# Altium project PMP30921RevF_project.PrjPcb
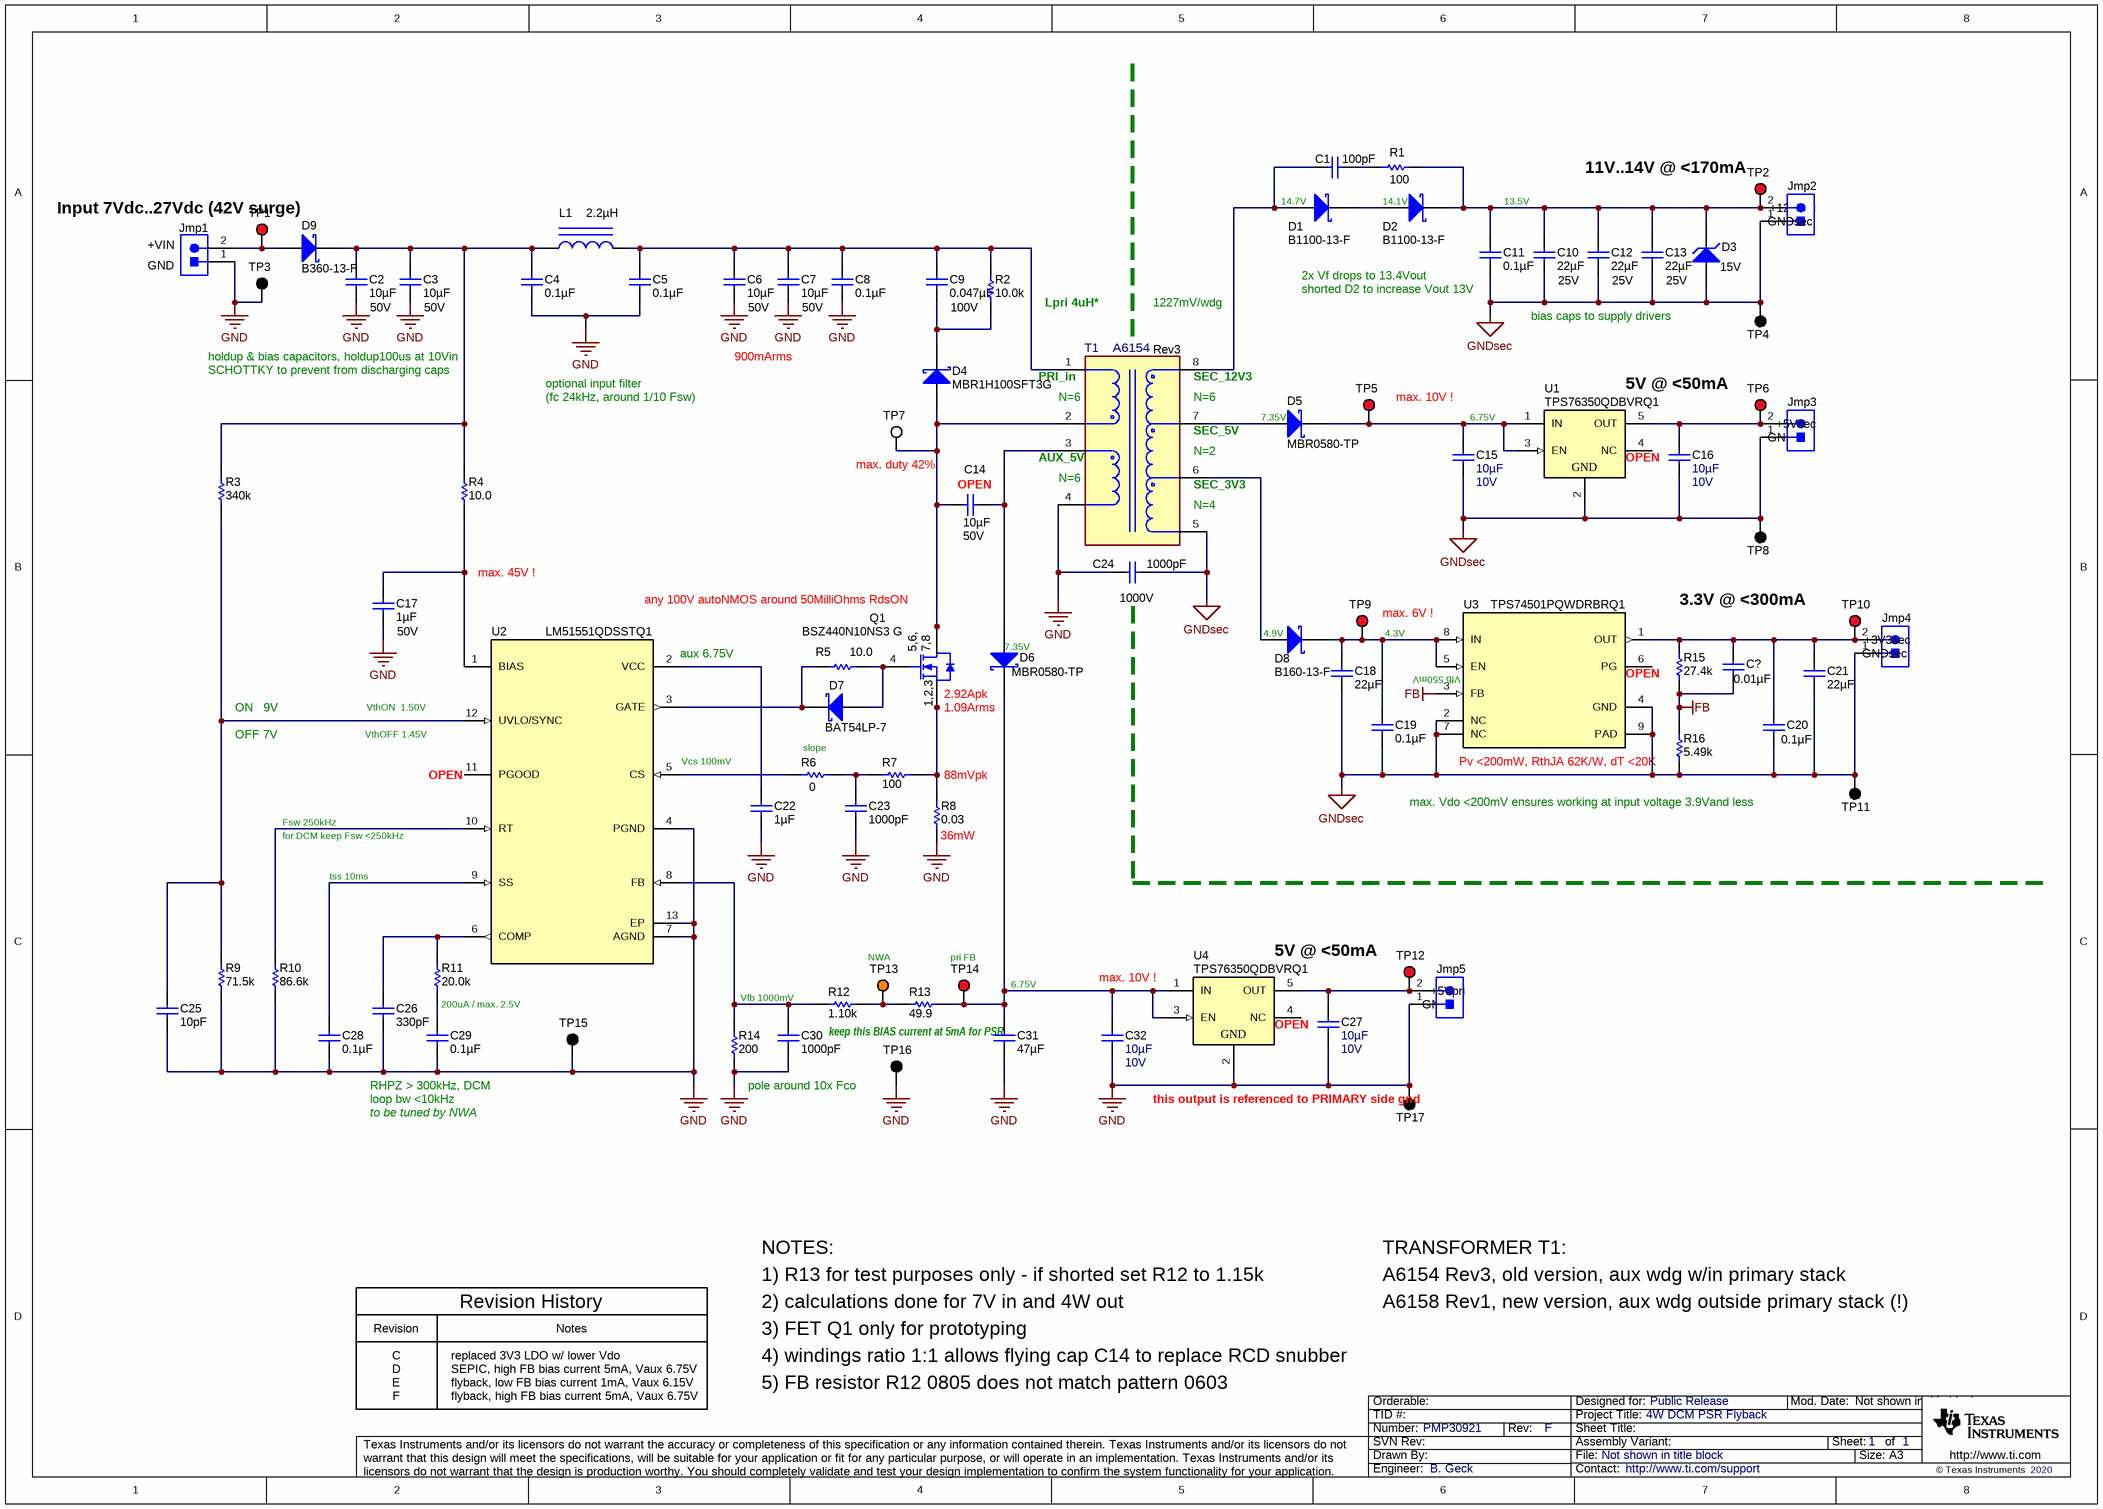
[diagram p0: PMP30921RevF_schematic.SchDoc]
CopyrightYear: 2020; PCB_Layout: B. Geck; PCB_Rev: C; PRJ_Customer: Public Release; PRJ_Engineer: B. Geck; PRJ_Number: PMP30921; PRJ_Title: 4W DCM PSR Flyback; SCH_Rev: F; TechSupport: http://www.ti.com/support
1 sheet, 87 parts. Net scope: global (net labels, ports and power ports of the same name join across sheets).
Board file: PMP30921RevC_board.PcbDoc

## Sheet PMP30921RevF_schematic.SchDoc
size A3; Date: Not shown in title block; ApprovedBy: Not shown in title block; CheckedBy: Not shown in title block; Author: Not shown in title block; CompanyName: Not shown in title block; Engineer: Not shown in title block; Organization: Not shown in title block; Address1: Not shown in title block; Address2: Not shown in title block; Address3: Not shown in title block; Address4: Not shown in title block; DocumentNumber: 1; Revision: Use project parameter SCH_Rev; SheetNumber: 1; SheetTotal: 1; PageSetup: Record=PageOptions¦CenterHorizontal=True¦CenterVertical=True¦PrintScale=0.68¦XCorrection=1.00¦YCorrection=1.00¦PrintKind=0¦BorderSize=5000000¦LeftOffset=0¦BottomOffset=0¦Orientation=2¦PaperLength=1000¦PaperWidth=1000¦Scale=100¦PaperSource=15¦PrintQuality=600¦MediaType=1¦DitherType=10¦PrintScaleMode=1¦PaperKind=A4¦PaperIndex=9

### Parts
C1  ValueDisplayed: 100pF  [0603]  (hidden comment: GRM1885C2A101JA01D)
C2  ValueDisplayed: 10µF  Value2: 50V  [1210_270]  (hidden comment: GRM32ER71H106KA12L)
C3  ValueDisplayed: 10µF  Value2: 50V  [1210_270]  (hidden comment: GRM32ER71H106KA12L)
C4  ValueDisplayed: 0.1µF  [0603]  (hidden comment: GCM188R71H104KA57D)
C5  ValueDisplayed: 0.1µF  [0603]  (hidden comment: GCM188R71H104KA57D)
C6  ValueDisplayed: 10µF  Value2: 50V  [1210_270]  (hidden comment: GRM32ER71H106KA12L)
C7  ValueDisplayed: 10µF  Value2: 50V  [1210_270]  (hidden comment: GRM32ER71H106KA12L)
C8  ValueDisplayed: 0.1µF  [0603]  (hidden comment: GCM188R71H104KA57D)
C9  ValueDisplayed: 0.047µF  Value2: 100V  [0805_HV]  (hidden comment: GRM21BR72A473KA01L)
C10  ValueDisplayed: 22µF  Value2: 25V  [1210_270]  (hidden comment: GRM32ER71E226KE15L)
C11  ValueDisplayed: 0.1µF  [0603]  (hidden comment: GCM188R71H104KA57D)
C12  ValueDisplayed: 22µF  Value2: 25V  [1210_270]  (hidden comment: GRM32ER71E226KE15L)
C13  ValueDisplayed: 22µF  Value2: 25V  [1210_270]  (hidden comment: GRM32ER71E226KE15L)
C14  ValueDisplayed: 10µF  Value2: 50V  [1210_270]  (hidden comment: GRM32ER71H106KA12L)
C15  Cap_F: 10µF  VDC_V: 10V  [0603]  (hidden comment: GRM188Z71A106MA73D)
C16  Cap_F: 10µF  VDC_V: 10V  [0603]  (hidden comment: GRM188Z71A106MA73D)
C17  ValueDisplayed: 1µF  Value2: 50V  [0805_HV]  (hidden comment: GRM21BR71H105KA12L)
C18  ValueDisplayed: 22µF  [0805_HV]  (hidden comment: GRM21BZ71A226ME15L)
C19  ValueDisplayed: 0.1µF  [0603]  (hidden comment: GRM188R71C104KA01D)
C20  ValueDisplayed: 0.1µF  [0603]  (hidden comment: GRM188R71C104KA01D)
C21  ValueDisplayed: 22µF  [0805_HV]  (hidden comment: GRM21BZ71A226ME15L)
C22  ValueDisplayed: 1µF  [0603]  (hidden comment: GRM188R71C105KA12D)
C23  ValueDisplayed: 1000pF  [0603]  (hidden comment: GRM188R71E102KA01D)
C24  ValueDisplayed: 1000pF  Value2: 1000V  [1206]  (hidden comment: GRM31BR73A102KW01L)
C25  ValueDisplayed: 10pF  [0603]  (hidden comment: GRM1885C1H100JA01D)
C26  ValueDisplayed: 330pF  [0603]  (hidden comment: GRM188R71H331KA01D)
C27  Cap_F: 10µF  VDC_V: 10V  [0603]  (hidden comment: GRM188Z71A106MA73D)
C28  ValueDisplayed: 0.1µF  [0603]  (hidden comment: GRM188R71C104KA01D)
C29  ValueDisplayed: 0.1µF  [0603]  (hidden comment: GRM188R71E104KA01D)
C30  ValueDisplayed: 1000pF  [0603]  (hidden comment: GRM188R71E102KA01D)
C31  ValueDisplayed: 47µF  [1210_270]  (hidden comment: GRM32ER71A476KE15L)
C32  Cap_F: 10µF  VDC_V: 10V  [0603]  (hidden comment: GRM188Z71A106MA73D)
C33  ValueDisplayed: 0.01µF  [0603]  (hidden comment: GRM188R71E103KA01D)
D1  B1100-13-F  [SMA]
D2  B1100-13-F  [SMA]
D3  value 15V  [SOD-123]  (hidden comment: MMSZ5245B-7-F)
D4  MBR1H100SFT3G  [SOD-123FL]
D5  MBR0580-TP  [SOD-123]
D6  MBR0580-TP  [SOD-123]
D7  BAT54LP-7  [X1-DFN1006-2]
D8  B160-13-F  [SMA]
D9  B360-13-F  [SMC]
Jmp1  ED555/2DS  [TERM_BLK_ED555-2DS]  (value not drawn)
Jmp2  ED555/2DS  [TERM_BLK_ED555-2DS]  (value not drawn)
Jmp3  ED555/2DS  [TERM_BLK_ED555-2DS]  (value not drawn)
Jmp4  ED555/2DS  [TERM_BLK_ED555-2DS]  (value not drawn)
Jmp5  ED555/2DS  [TERM_BLK_ED555-2DS]  (value not drawn)
L1  ValueDisplayed: 2.2µH  [XEL4030_310]  (hidden comment: XEL4030-222MEB)
Q1  BSZ440N10NS3 G  [PG-TSDSON-8]
R1  ValueDisplayed: 100  [0805_HV]  (hidden comment: CRCW0805100RJNEA)
R2  ValueDisplayed: 10.0k  [1206]  (hidden comment: CRCW120610K0FKEAHP)
R3  ValueDisplayed: 340k  [0603]  (hidden comment: CRCW0603340KFKEA)
R4  ValueDisplayed: 10.0  [0603]  (hidden comment: CRCW060310R0FKEAHP)
R5  ValueDisplayed: 10.0  [0603]  (hidden comment: CRCW060310R0FKEA)
R6  ValueDisplayed: 0  [0603]  (hidden comment: CRCW06030000Z0EA)
R7  ValueDisplayed: 100  [0603]  (hidden comment: CRCW0603100RFKEA)
R8  ValueDisplayed: 0.03  [WSLP0805]  (hidden comment: WSLP0805R0300FEB)
R9  ValueDisplayed: 71.5k  [0603]  (hidden comment: CRCW060371K5FKEA)
R10  ValueDisplayed: 86.6k  [0603]  (hidden comment: CRCW060386K6FKEA)
R11  ValueDisplayed: 20.0k  [0603]  (hidden comment: CRCW060320K0FKEA)
R12  ValueDisplayed: 1.10k  [0805_HV]  (hidden comment: CRCW08051K10FKEA)
R13  ValueDisplayed: 49.9  [0603]  (hidden comment: CRCW060349R9FKEA)
R14  ValueDisplayed: 200  [0603]  (hidden comment: CRCW0603200RFKEA)
R15  ValueDisplayed: 27.4k  [0603]  (hidden comment: CRCW060327K4FKEA)
R16  ValueDisplayed: 5.49k  [0603]  (hidden comment: CRCW06035K49FKEA)
T1  A6154  [FP-A6154_PTH_XFRMR_9MM7_13MM0-MFG]
TP1  5000  [Keystone5000]  (value not drawn)
TP2  5000  [Keystone5000]  (value not drawn)
TP3  5001  [Keystone5001]  (value not drawn)
TP4  5001  [Keystone5001]  (value not drawn)
TP5  5000  [Keystone5000]  (value not drawn)
TP6  5000  [Keystone5000]  (value not drawn)
TP7  5002  [Keystone5002]  (value not drawn)
TP8  5001  [Keystone5001]  (value not drawn)
TP9  5000  [Keystone5000]  (value not drawn)
TP10  5000  [Keystone5000]  (value not drawn)
TP11  5001  [Keystone5001]  (value not drawn)
TP12  5000  [Keystone5000]  (value not drawn)
TP13  5003  [Keystone5003]  (value not drawn)
TP14  5000  [Keystone5000]  (value not drawn)
TP15  5001  [Keystone5001]  (value not drawn)
TP16  5001  [Keystone5001]  (value not drawn)
TP17  5001  [Keystone5001]  (value not drawn)
U1  TPS76350QDBVRQ1  [DBV0005A_N]
U2  LM51551QDSSTQ1  [DSS0012C]
U3  TPS74501PQWDRBRQ1  [DRB0008J]
U4  TPS76350QDBVRQ1  [DBV0005A_N]

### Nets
FB: C33.2 R15.1 R16.2 U3.3(FB)
GND: C2.2 C3.2 C4.2 C5.2 C6.2 C7.2 C8.2 C17.2 C22.2 C23.2 C24.2 C25.2 C26.2 C27.2 C28.2 C29.2 C30.2 C31.2 C32.2 Jmp1.1 Jmp5.1 R8.1 R9.1 R10.1 R14.1 T1.4 TP3.1 TP15.1 TP16.1 TP17.1 U2.4(PGND) U2.7(AGND) U2.13(EP) U4.2(GND)
GNDsec: C10.2 C11.2 C12.2 C13.2 C15.2 C16.2 C18.2 C19.2 C20.2 C21.2 C24.1 D3.2(A) Jmp2.1 Jmp3.1 Jmp4.1 R16.1 T1.5 TP4.1 TP8.1 TP11.1 U1.2(GND) U3.2(NC) U3.4(GND) U3.7(NC) U3.9(PAD)
NetC1_1: C1.1 R1.1
NetC1_2: C1.2 D1.2(A) T1.8
NetC2_1: C2.1 C3.1 C4.1 D9.1(K) L1.1 R3.2 R4.2
NetC5_1: C5.1 C6.1 C7.1 C8.1 C9.1 L1.2 R2.2 T1.1
NetC9_2: C9.2 D4.1(K) R2.1
NetC10_1: C10.1 C11.1 C12.1 C13.1 D2.1(K) D3.1(K) Jmp2.2 R1.2 TP2.1
NetC14_1: C14.1 D4.2(A) Q1.5(D) Q1.6(D) Q1.7(D) Q1.8(D) Q1.9(D) T1.2 TP7.1
NetC14_2: C14.2 D6.2(A) T1.3
NetC15_1: C15.1 D5.1(K) TP5.1 U1.1(IN) U1.3(EN)
NetC16_1: C16.1 Jmp3.2 TP6.1 U1.5(OUT)
NetC17_1: C17.1 R4.1 U2.1(BIAS)
NetC18_1: C18.1 C19.1 D8.1(K) TP9.1 U3.5(EN) U3.8(IN)
NetC20_1: C20.1 C21.1 C33.1 Jmp4.2 R15.2 TP10.1 U3.1(OUT)
NetC22_1: C22.1 U2.2(VCC)
NetC23_1: C23.1 R6.2 R7.1
NetC25_1: C25.1 R3.1 R9.2 U2.12(UVLO/SYNC)
NetC26_1: C26.1 R11.2 U2.6(COMP)
NetC27_1: C27.1 Jmp5.2 TP12.1 U4.5(OUT)
NetC28_1: C28.1 U2.9(SS)
NetC29_1: C29.1 R11.1
NetC30_1: C30.1 R12.1 R14.2 U2.8(FB)
NetC31_1: C31.1 C32.1 D6.1(K) R13.2 TP14.1 U4.1(IN) U4.3(EN)
NetD1_1: D1.1(K) D2.2(A)
NetD5_2: D5.2(A) T1.7
NetD7_1: D7.1(K) R5.1 U2.3(GATE)
NetD7_2: D7.2(A) Q1.4(G) R5.2
NetD8_2: D8.2(A) T1.6
NetD9_2: D9.2(A) Jmp1.2 TP1.1
NetQ1_1: Q1.1(S) Q1.2(S) Q1.3(S) R7.2 R8.2
NetR6_1: R6.1 U2.5(CS)
NetR10_2: R10.2 U2.10(RT)
NetR12_2: R12.2 R13.1 TP13.1

Not connected (* = marked no-connect by the designer): U1 4(NC); U2 11(PGOOD); U3 6(PG); U4 4(NC)

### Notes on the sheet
- (near TP2) 11V..14V @ <170mA
- (near Jmp1) +VIN
- Input 7Vdc..27Vdc (42V surge)
- (near D1) 14.7V
- (near D2) 14.1V
- 13.5V
- (near Jmp2) GNDsec
- (near Jmp2) +12Vsec
- (near Jmp1) GND
- Lpri 4uH*
- 1227mV/wdg
- 2x Vf drops to 13.4Vout
- (near C11) shorted D2 to increase Vout 13V
- bias caps to supply drivers
- holdup & bias capacitors, holdup100us at 10Vin
- SCHOTTKY to prevent from discharging caps
- optional input filter
- 900mArms
- (near T1) PRI_in
- (near T1) Rev3
- (near T1) SEC_12V3
- (near U1) 5V @ <50mA
- (fc 24kHz, around 1/10 Fsw)
- (near T1) AUX_5V
- (near T1) N=6
- (near T1) SEC_5V
- (near T1) N=2
- (near D5) 7.35V
- (near TP5) max. 10V !
- (near C15) 6.75V
- (near U1) OPEN
- (near Jmp3) GNDsec
- (near Jmp3) +5Vsec
- (near TP7) max. duty 42%
- (near C14) OPEN
- (near T1) N=4
- (near T1) SEC_3V3
- max. 45V !
- (near U2) aux 6.75V
- any 100V autoNMOS around 50MilliOhms RdsON
- (near D6) 7.35V
- (near D8) 4.9V
- max. 6V !
- (near TP9) 4.3V
- 3.3V @ <300mA
- (near Jmp4) GNDsec
- (near Jmp4) +3V3sec
- ON   9V
- VthON  1.50V
- (near Q1) 2.92Apk
- 1.09Arms
- (near U3) Vfb 550mV
- (near U3) OPEN
- OFF 7V
- VthOFF 1.45V
- (near U2) OPEN
- Vcs 100mV
- slope
- 88mVpk
- Pv <200mW, RthJA 62K/W, dT <20K
- Fsw 250kHz
- for DCM keep Fsw <250kHz
- (near R8) 36mW
- (near R16) max. Vdo <200mV ensures working at input voltage 3.9Vand less
- tss 10ms
- Vfb 1000mV
- NWA
- pri FB
- 6.75V
- max. 10V !
- (near U4) 5V @ <50mA
- (near Jmp5) +5Vpri
- (near R11) 200uA / max. 2.5V
- (near C31) keep this BIAS current at 5mA for PSR
- (near U4) OPEN
- (near Jmp5) GNDpri
- RHPZ > 300kHz, DCM
- loop bw <10kHz
- to be tuned by NWA
- pole around 10x Fco
- (near TP17) this output is referenced to PRIMARY side gnd
- NOTES:
- TRANSFORMER T1:
- Revision
- Revision History
- Notes
- 1) R13 for test purposes only - if shorted set R12 to 1.15k
- 2) calculations done for 7V in and 4W out
- 3) FET Q1 only for prototyping
- A6154 Rev3, old version, aux wdg w/in primary stack
- A6158 Rev1, new version, aux wdg outside primary stack (!)
- C
- D
- E
- F
- replaced 3V3 LDO w/ lower Vdo
- flyback, low FB bias current 1mA, Vaux 6.15V
- flyback, high FB bias current 5mA, Vaux 6.75V
- SEPIC, high FB bias current 5mA, Vaux 6.75V
- 4) windings ratio 1:1 allows flying cap C14 to replace RCD snubber
- 5) FB resistor R12 0805 does not match pattern 0603

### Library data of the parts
C1 = GRM1885C2A101JA01D: CAP, CERM, 100 pF, 100 V,+/- 5%, C0G/NP0, 0603; Manufacturer: MuRata; Polarized: N; CompType: Capacitor; Value: 100pF; U/M: EA; Cap_F: 0.0000000001; Tolerance_%: 5; VDC_V: 100; Value2: 100V; TaMin_C: -55; TaMax_C: 125; SizeArea_mm2: 1.28; SizeAreaWB_mm2: 4.68; SizeX_mm: 1.6; SizeY_mm: 0.8; SizeZ_mm: 1; AEC Category: Q200; Green_Lifecycle: Active; Green_REACh: Passed
C2 C3 C6 C7 C14 = GRM32ER71H106KA12L: CAP, CERM, 10 µF, 50 V,+/- 10%, X7R, 1210; Manufacturer: MuRata; Polarized: N; CompType: Capacitor; Value: 10uF; U/M: EA; Cap_F: 0.00001; Tolerance_%: 10; VDC_V: 50; TaMin_C: -55; TaMax_C: 125; Cap_Case: 1210; SizeArea_mm2: 8; SizeAreaWB_mm2: 14.7; SizeX_mm: 3.2; SizeY_mm: 2.5; SizeZ_mm: 2.7; AEC Category: Q200; Green_Lifecycle: Active; Green_REACh: Passed
C4 C5 C8 C11 = GCM188R71H104KA57D: CAP, CERM, 0.1 µF, 50 V, +/- 10%, X7R, 0603; Manufacturer: MuRata; Polarized: N; CompType: Capacitor; Value: 0.1uF; U/M: EA; Cap_F: 0.0000001; Tolerance_%: 10; ESR_ohm: 0.02; Value1: 0.02 ohm; VDC_V: 50; Value2: 50V; IRMS_A: 1.84; TaMin_C: -55; TaMax_C: 125; AEC Category: Q200
C9 = GRM21BR72A473KA01L: CAP, CERM, 0.047 µF, 100 V,+/- 10%, X7R, 0805; Manufacturer: MuRata; Polarized: N; CompType: Capacitor; Value: 0.047uF; U/M: EA; Cap_F: 0.000000047; Tolerance_%: 10; VDC_V: 100; TaMin_C: -55; TaMax_C: 125; Cap_Case: 0805; SizeArea_mm2: 2.5; SizeAreaWB_mm2: 6.75; SizeX_mm: 2; SizeY_mm: 1.25; SizeZ_mm: 1.45; AEC Category: Q200
C10 C12 C13 = GRM32ER71E226KE15L: CAP, CERM, 22 µF, 25 V,+/- 10%, X7R, 1210; Manufacturer: MuRata; Polarized: N; CompType: Capacitor; Value: 22uF; U/M: EA; Cap_F: 0.000022; Tolerance_%: 10; ESR_ohm: 0.002334; Value1: 0.002334 ohm; VDC_V: 25; IRMS_A: 3.832999; TaMin_C: -55; TaMax_C: 125; Cap_Case: 1210; SizeArea_mm2: 8; SizeAreaWB_mm2: 14.7; SizeX_mm: 3.2; SizeY_mm: 2.5; SizeZ_mm: 2.7; AEC Category: Q200; Green_Lifecycle: Active; Green_REACh: Passed
C15 C16 C27 C32 = CMP-0007497-5: CAP, CERM, 10 uF, 10 V, +/- 20%, X7R, 0603; Manufacturer: MuRata; TaMin_C: -55°C; Polarized: N; SizeAreaWB_mm2: 4.68; Value1: Unknown; U/M: EA; Value: 10uF; TaMax_C: 125°C; SizeZ_mm: 1; SizeX_mm: 1.6; SizeY_mm: 0.8; SizeArea_mm2: 1.28; AEC Category: Q200
C17 = GRM21BR71H105KA12L: CAP, CERM, 1 µF, 50 V,+/- 10%, X7R, 0805; Manufacturer: MuRata; Polarized: N; CompType: Capacitor; Value: 1uF; U/M: EA; Cap_F: 0.000001; Tolerance_%: 10; VDC_V: 50; TaMin_C: -55; TaMax_C: 125; Cap_Case: 0805; SizeArea_mm2: 2.5; SizeAreaWB_mm2: 6.75; SizeX_mm: 2; SizeY_mm: 1.25; SizeZ_mm: 1.45; AEC Category: Q200; Green_Lifecycle: Active; Green_REACh: Passed
C18 C21 = GRM21BZ71A226ME15L: CAP, CERM, 22 µF, 10 V,+/- 20%, X7R, 0805; Manufacturer: MuRata; Polarized: N; CompType: Capacitor; Value: 22uF; U/M: EA; Cap_F: 0.000022; Tolerance_%: 20; VDC_V: 10; Value2: 10V; TaMin_C: -55; TaMax_C: 125; Cap_Case: 0805; SizeArea_mm2: 2.5; SizeAreaWB_mm2: 6.75; SizeX_mm: 2; SizeY_mm: 1.25; SizeZ_mm: 1.45; AEC Category: Q200
C19 C20 C28 = GRM188R71C104KA01D: CAP, CERM, 0.1 µF, 16 V,+/- 10%, X7R, 0603; Manufacturer: MuRata; Polarized: N; CompType: Capacitor; Value: 0.1uF; U/M: EA; Cap_F: 0.0000001; Tolerance_%: 10; VDC_V: 16; Value2: 16V; TaMin_C: -55; TaMax_C: 125; SizeArea_mm2: 1.28; SizeAreaWB_mm2: 4.68; SizeX_mm: 1.6; SizeY_mm: 0.8; SizeZ_mm: 1; AEC Category: Q200; Green_Lifecycle: Active; Green_REACh: Passed
C22 = GRM188R71C105KA12D: CAP, CERM, 1 µF, 16 V, +/- 10%, X7R, 0603; Manufacturer: MuRata; Polarized: N; CompType: Capacitor; Value: 1uF; U/M: EA; Cap_F: 0.000001; Tolerance_%: 10; ESR_ohm: 0.011; Value1: 0.011 ohm; VDC_V: 16; Value2: 16V; TaMin_C: -55; TaMax_C: 125; AEC Category: Q200
C23 C30 = GRM188R71E102KA01D: CAP, CERM, 1000 pF, 25 V,+/- 10%, X7R, 0603; Manufacturer: MuRata; Polarized: N; CompType: Capacitor; Value: 1000pF; U/M: EA; Cap_F: 0.000000001; Tolerance_%: 10; VDC_V: 25; Value2: 25V; TaMin_C: -55; TaMax_C: 125; SizeArea_mm2: 1.28; SizeAreaWB_mm2: 4.68; SizeX_mm: 1.6; SizeY_mm: 0.8; SizeZ_mm: 1; AEC Category: Q200; Green_Lifecycle: Active; Green_REACh: Passed
C24 = GRM31BR73A102KW01L: CAP, CERM, 1000 pF, 1000 V,+/- 10%, X7R, 1206; Manufacturer: MuRata; Polarized: N; CompType: Capacitor; Value: 1000pF; U/M: EA; Cap_F: 0.000000001; Tolerance_%: 10; VDC_V: 1000; TaMin_C: -55; TaMax_C: 125; SizeArea_mm2: 5.12; SizeAreaWB_mm2: 10.92; SizeX_mm: 3.2; SizeY_mm: 1.6; SizeZ_mm: 1.35; AEC Category: Q200; Green_Lifecycle: Not Set; Green_REACh: Incomplete
C25 = GRM1885C1H100JA01D: CAP, CERM, 10 pF, 50 V,+/- 5%, C0G/NP0, 0603; Manufacturer: MuRata; Polarized: N; CompType: Capacitor; Value: 10pF; U/M: EA; Cap_F: 0.00000000001; Tolerance_%: 5; VDC_V: 50; Value2: 50V; TaMin_C: -55; TaMax_C: 125; SizeArea_mm2: 1.28; SizeAreaWB_mm2: 4.68; SizeX_mm: 1.6; SizeY_mm: 0.8; SizeZ_mm: 1; AEC Category: Q200; Green_Lifecycle: Active; Green_REACh: Passed
C26 = GRM188R71H331KA01D: CAP, CERM, 330 pF, 50 V,+/- 10%, X7R, 0603; Manufacturer: MuRata; Polarized: N; CompType: Capacitor; Value: 330pF; U/M: EA; Cap_F: 0.00000000033; Tolerance_%: 10; VDC_V: 50; Value2: 50V; TaMin_C: -55; TaMax_C: 125; SizeArea_mm2: 1.28; SizeAreaWB_mm2: 4.68; SizeX_mm: 1.6; SizeY_mm: 0.8; SizeZ_mm: 1; AEC Category: Q200; Green_Lifecycle: Active; Green_REACh: Passed
C29 = GRM188R71E104KA01D: CAP, CERM, 0.1 µF, 25 V,+/- 10%, X7R, 0603; Manufacturer: MuRata; Polarized: N; CompType: Capacitor; Value: 0.1uF; U/M: EA; Cap_F: 0.0000001; Tolerance_%: 10; VDC_V: 25; Value2: 25V; TaMin_C: -55; TaMax_C: 125; SizeArea_mm2: 1.28; SizeAreaWB_mm2: 4.68; SizeX_mm: 1.6; SizeY_mm: 0.8; SizeZ_mm: 1; AEC Category: Q200; Green_Lifecycle: Active; Green_REACh: Passed
C31 = GRM32ER71A476KE15L: CAP, CERM, 47 µF, 10 V,+/- 10%, X7R, 1210; Manufacturer: MuRata; Polarized: N; CompType: Capacitor; Value: 47uF; U/M: EA; Cap_F: 0.000047; Tolerance_%: 10; Value2: 10V; TaMin_C: -55; TaMax_C: 125; Cap_Case: 1210; SizeArea_mm2: 8; SizeAreaWB_mm2: 14.7; SizeX_mm: 3.2; SizeY_mm: 2.5; SizeZ_mm: 2.7; AEC Category: Q200; Green_Lifecycle: Active; Green_REACh: Passed
C33 = GRM188R71E103KA01D: CAP, CERM, 0.01 µF, 25 V,+/- 10%, X7R, 0603; Manufacturer: MuRata; Polarized: N; CompType: Capacitor; Value: 0.01uF; U/M: EA; Cap_F: 0.00000001; Tolerance_%: 10; VDC_V: 25; Value2: 25V; TaMin_C: -55; TaMax_C: 125; SizeArea_mm2: 1.28; SizeAreaWB_mm2: 4.68; SizeX_mm: 1.6; SizeY_mm: 0.8; SizeZ_mm: 1; AEC Category: Q200; Green_Lifecycle: Active; Green_REACh: Passed
D1 D2 = B1100-13-F: Diode, Schottky, 100 V, 1 A, SMA; Manufacturer: Diodes Inc.; U/M: EA; Vf_V: 0.79; Value: 100V; Value1: 1A; Value2: 0.79V; Io_A: 1; Vr_V: 100; TJmax_C: 150; RJC_CperW: 25; SizeAreaWB_mm2: 37.3428; SizeArea_mm2: 16.3228; SizeX_mm: 5.59; SizeY_mm: 2.92; SizeZ_mm: 2.87; AEC Category: Q101; Green_Lifecycle: Active; Green_REACh: Passed
D3 = MMSZ5245B-7-F: Diode, Zener, 15 V, 500 mW, SOD-123; Manufacturer: Diodes Inc.; SymbolCreator: a0412235; U/M: EA; Power_W: 0.5; Vz_V: 15; Value1: 0.5W; RJA_CperW: 350; SizeAreaWB_mm2: 13.095; SizeArea_mm2: 6.545; SizeX_mm: 3.85; SizeY_mm: 1.7; SizeZ_mm: 1.35; AEC Category: Q101; Green_Lifecycle: Active; Green_REACh: Passed
D4 = MBR1H100SFT3G: Diode, Schottky, 100 V, 1 A, SOD-123FL; Manufacturer: ON Semiconductor; U/M: EA; Vf_V: 0.76; Value: 100V; Value1: 1A; Value2: 0.76V; Io_A: 1; Vr_V: 100; TJmax_C: 175; RJC_CperW: 85; SizeAreaWB_mm2: 12.19; SizeArea_mm2: 5.94; SizeX_mm: 3.6; SizeY_mm: 1.65; SizeZ_mm: 0.98; AEC Category: Q101; Green_Lifecycle: Active; Green_REACh: Passed
D5 D6 = MBR0580-TP: Diode, Schottky, 80 V, 0.5 A, SOD-123; Manufacturer: Micro Commercial Components; U/M: EA; Vf_V: 0.8; Value: 80V; Value1: 0.5A; Value2: 0.8V; Io_A: 0.5; Vr_V: 80; TJmax_C: 150; SizeAreaWB_mm2: 13.095; SizeArea_mm2: 6.545; SizeX_mm: 3.85; SizeY_mm: 1.7; SizeZ_mm: 1.35; AEC Category: Q101; Green_Lifecycle: Not Set; Green_REACh: Incomplete
D7 = BAT54LP-7: Diode, Schottky, 30 V, 0.2 A, 1.00x0.50x0.60mm; Manufacturer: Diodes Inc.; U/M: EA; Vf_V: 1; Value: 30V; Value1: 0.2A; Value2: 1V; Io_A: 0.2; Vr_V: 30; SizeAreaWB_mm2: 3.2; SizeArea_mm2: 0.6; SizeZ_mm: 0.53; AEC Category: Q101; Green_Lifecycle: Not Set; Green_REACh: Incomplete
D8 = B160-13-F: Diode, Schottky, 60 V, 1 A, SMA; Manufacturer: Diodes Inc.; U/M: EA; Vf_V: 0.7; Value: 60V; Value1: 1A; Value2: 0.7V; Io_A: 1; Vr_V: 60; TJmax_C: 150; RJC_CperW: 20; SizeAreaWB_mm2: 37.3428; SizeArea_mm2: 16.3228; SizeX_mm: 5.59; SizeY_mm: 2.92; SizeZ_mm: 2.87; AEC Category: Q101; Green_Lifecycle: Not Set; Green_REACh: Incomplete
D9 = B360-13-F: Diode, Schottky, 60 V, 3 A, SMC; Manufacturer: Diodes Inc.; U/M: EA; Vf_V: 0.7; Value: 60V; Value1: 3A; Value2: 0.7V; Io_A: 3; Vr_V: 60; TJmax_C: 125; RJC_CperW: 20; SizeAreaWB_mm2: 83.2686; SizeArea_mm2: 50.5686; SizeX_mm: 8.13; SizeY_mm: 6.22; SizeZ_mm: 2.6; AEC Category: Q101; Green_Lifecycle: Not Set; Green_REACh: Incomplete
Jmp1-Jmp5 = ED555/2DS: Terminal Block, 6A, 3.5mm Pitch, 2-Pos, TH; Manufacturer: On-Shore Technology; SymbolCreator: a0412235; CompType: Connector; U/M: EA
L1 = XEL4030-222MEB: Inductor, Shielded, Composite, 2.2 µH, 6.1 A, 0.0201 ohm, AEC-Q200 Grade 1, SMD; Manufacturer: Coilcraft; Value: 2.2uH; Ind_H: 2.2E-6; Imax_A: 6.1; Irms: 7.8A @ 40C rise; Isat: 6.1A @ 30% inductance drop; DCR_ohm: 0.0201; Value2: 6.1A; SizeAreaWB_mm2: 25; SizeArea_mm2: 16; SizeX_mm: 4; SizeZ_mm: 3.1; AEC Category: Q200; AEC Qualified: Y; AEC Grade: 1
Q1 = BSZ440N10NS3 G: MOSFET, N-CH, 100 V, 18 A, PG-TSDSON-8; Manufacturer: Infineon Technologies; Alternate Manufacturer: None; U/M: EA; ChType: N; Value: 100V; VdsMax_V: 100; Value1: ? ohm; Value2: 6.8 nC; QgTyp_nC: 6.8; Vgs_V: 20; IdsMax_A: 18; SizeAreaWB_mm2: 19.36; SizeArea_mm2: 11.56; SizeX_mm: 3.4; SizeZ_mm: 1.1; AEC Category: Q101; Green_Lifecycle: Not Set; Green_REACh: Incomplete
R1 = CRCW0805100RJNEA: RES, 100, 5%, 0.125 W, 0805; Manufacturer: Vishay-Dale; CompType: Resistor; Value: 100; Value_Code: 100R; Tolerance_%: 5; Power_W: 0.125; Value2: 0.125W; VDC_V: 150; TempCo: 200 ppm/C; SizeArea_mm2: 2.5; SizeX_mm: 2; SizeY_mm: 1.25; SizeZ_mm: 1.45; EIA_Code: E24; U/M: EA; AEC Category: Q200
R2 = CRCW120610K0FKEAHP: RES, 10.0 k, 1%, 0.5 W, 1206; Manufacturer: Vishay-Dale; CompType: Resistor; Value: 10.0k; Res_ohm: 10000; Value_Code: 10k0; Tolerance_%: 1; Power_W: 0.5; Value2: 0.5W; TempCo: 100 ppm/C; SizeArea_mm2: 5.12; SizeX_mm: 3.2; SizeY_mm: 1.6; SizeZ_mm: 1.35; EIA_Code: E96; U/M: EA; AEC Category: Q200
R3 = CRCW0603340KFKEA: RES, 340 k, 1%, 0.1 W, 0603; Manufacturer: Vishay-Dale; CompType: Resistor; Value: 340k; Res_ohm: 340000; Tolerance_%: 1; Power_W: 0.1; Value2: 0.1W; VDC_V: 75; TempCo: 100 ppm/C; SizeArea_mm2: 1.28; SizeX_mm: 1.6; SizeY_mm: 0.8; EIA_Code: E96; U/M: EA; AEC Category: Q200; Green_Lifecycle: Active; Green_REACh: Passed
R4 = CRCW060310R0FKEAHP: RES, 10.0, 1%, 0.25 W, 0603; Manufacturer: Vishay-Dale; CompType: Resistor; Value: 10.0; Res_ohm: 10; Value_Code: 10R0; Tolerance_%: 1; Power_W: 0.25; Value2: 0.25W; VDC_V: 75; TempCo: 100 ppm/C; SizeArea_mm2: 1.28; SizeX_mm: 1.6; SizeY_mm: 0.8; EIA_Code: E96; U/M: EA; AEC Category: Q200; Green_Lifecycle: Active; Green_REACh: Passed
R5 = CRCW060310R0FKEA: RES, 10.0, 1%, 0.1 W, 0603; Manufacturer: Vishay-Dale; CompType: Resistor; Value: 10.0; Res_ohm: 10; Value_Code: 10R0; Tolerance_%: 1; Power_W: 0.1; Value2: 0.1W; VDC_V: 75; TempCo: 100 ppm/C; SizeArea_mm2: 1.28; SizeX_mm: 1.6; SizeY_mm: 0.8; EIA_Code: E96; U/M: EA; AEC Category: Q200; Green_Lifecycle: Active; Green_REACh: Passed
R6 = CRCW06030000Z0EA: RES, 0, 5%, 0.1 W, 0603; Manufacturer: Vishay-Dale; CompType: Resistor; Value: 0; Value_Code: 0000; Tolerance_%: 5; Power_W: 0.1; Value2: 0.1W; VDC_V: 75; TempCo: 200 ppm/C; SizeArea_mm2: 1.28; SizeX_mm: 1.6; SizeY_mm: 0.8; SizeZ_mm: 1; EIA_Code: E24; U/M: EA; AEC Category: Q200; Green_Lifecycle: Active; Green_REACh: Passed
R7 = CRCW0603100RFKEA: RES, 100, 1%, 0.1 W, 0603; Manufacturer: Vishay-Dale; CompType: Resistor; Value: 100; Value_Code: 100R; Tolerance_%: 1; Power_W: 0.1; Value2: 0.1W; VDC_V: 75; TempCo: 100 ppm/C; SizeArea_mm2: 1.28; SizeX_mm: 1.6; SizeY_mm: 0.8; EIA_Code: E96; U/M: EA; AEC Category: Q200; Green_Lifecycle: Active; Green_REACh: Passed
R8 = WSLP0805R0300FEB: RES, 0.03, 1%, 0.5 W, 0805; Manufacturer: Vishay-Dale; CompType: Resistor; Value: 0.03; Value_Code: R030; Tolerance_%: 1; Power_W: 0.5; Value2: 0.5W; TempCo: 75 ppm/C; SizeArea_mm2: 2.5781; SizeX_mm: 2.03; SizeY_mm: 1.27; SizeZ_mm: 0.635; EIA_Code: E96; U/M: EA; AEC Category: Q200; AEC Qualified: N
R9 = CRCW060371K5FKEA: RES, 71.5 k, 1%, 0.1 W, 0603; Manufacturer: Vishay-Dale; CompType: Resistor; Value: 71.5k; Res_ohm: 71500; Value_Code: 71k5; Tolerance_%: 1; Power_W: 0.1; Value2: 0.1W; VDC_V: 75; TempCo: 100 ppm/C; SizeArea_mm2: 1.28; SizeX_mm: 1.6; SizeY_mm: 0.8; EIA_Code: E96; U/M: EA; AEC Category: Q200; Green_Lifecycle: Active; Green_REACh: Passed
R10 = CRCW060386K6FKEA: RES, 86.6 k, 1%, 0.1 W, 0603; Manufacturer: Vishay-Dale; CompType: Resistor; Value: 86.6k; Res_ohm: 86600; Value_Code: 86k6; Tolerance_%: 1; Power_W: 0.1; Value2: 0.1W; VDC_V: 75; TempCo: 100 ppm/C; SizeArea_mm2: 1.28; SizeX_mm: 1.6; SizeY_mm: 0.8; EIA_Code: E96; U/M: EA; AEC Category: Q200; Green_Lifecycle: Active; Green_REACh: Passed
R11 = CRCW060320K0FKEA: RES, 20.0 k, 1%, 0.1 W, 0603; Manufacturer: Vishay-Dale; CompType: Resistor; Value: 20.0k; Res_ohm: 20000; Value_Code: 20k0; Tolerance_%: 1; Power_W: 0.1; Value2: 0.1W; VDC_V: 75; TempCo: 100 ppm/C; SizeArea_mm2: 1.28; SizeX_mm: 1.6; SizeY_mm: 0.8; EIA_Code: E96; U/M: EA; AEC Category: Q200; Green_Lifecycle: Active; Green_REACh: Passed
R12 = CRCW08051K10FKEA: RES, 1.10 k, 1%, 0.125 W, 0805; Manufacturer: Vishay-Dale; CompType: Resistor; Value: 1.10k; Res_ohm: 1100; Value_Code: 1k10; Tolerance_%: 1; Power_W: 0.125; Value2: 0.125W; VDC_V: 150; TempCo: 100 ppm/C; SizeArea_mm2: 2.5; SizeX_mm: 2; SizeY_mm: 1.25; SizeZ_mm: 1.45; EIA_Code: E96; U/M: EA; AEC Category: Q200; Green_Lifecycle: Active; Green_REACh: Passed
R13 = CRCW060349R9FKEA: RES, 49.9, 1%, 0.1 W, 0603; Manufacturer: Vishay-Dale; CompType: Resistor; Value: 49.9; Value_Code: 49R9; Tolerance_%: 1; Power_W: 0.1; Value2: 0.1W; VDC_V: 75; TempCo: 100 ppm/C; SizeArea_mm2: 1.28; SizeX_mm: 1.6; SizeY_mm: 0.8; EIA_Code: E96; U/M: EA; AEC Category: Q200
R14 = CRCW0603200RFKEA: RES, 200, 1%, 0.1 W, 0603; Manufacturer: Vishay-Dale; CompType: Resistor; Value: 200; Value_Code: 200R; Tolerance_%: 1; Power_W: 0.1; Value2: 0.1W; VDC_V: 75; TempCo: 100 ppm/C; SizeArea_mm2: 1.28; SizeX_mm: 1.6; SizeY_mm: 0.8; EIA_Code: E96; U/M: EA; AEC Category: Q200; Green_Lifecycle: Active; Green_REACh: Passed
R15 = CRCW060327K4FKEA: RES, 27.4 k, 1%, 0.1 W, 0603; Manufacturer: Vishay-Dale; CompType: Resistor; Value: 27.4k; Res_ohm: 27400; Value_Code: 27k4; Tolerance_%: 1; Power_W: 0.1; Value2: 0.1W; VDC_V: 75; TempCo: 100 ppm/C; SizeArea_mm2: 1.28; SizeX_mm: 1.6; SizeY_mm: 0.8; EIA_Code: E96; U/M: EA; AEC Category: Q200; Green_Lifecycle: Active; Green_REACh: Passed
R16 = CRCW06035K49FKEA: RES, 5.49 k, 1%, 0.1 W, 0603; Manufacturer: Vishay-Dale; CompType: Resistor; Value: 5.49k; Res_ohm: 5490; Value_Code: 5k49; Tolerance_%: 1; Power_W: 0.1; Value2: 0.1W; VDC_V: 75; TempCo: 100 ppm/C; SizeArea_mm2: 1.28; SizeX_mm: 1.6; SizeY_mm: 0.8; EIA_Code: E96; U/M: EA; AEC Category: Q200; Green_Lifecycle: Active; Green_REACh: Passed
T1 = CMP-0090554-1: TRANSFORMER; Manufacturer: MPS Industries; SizeZ_mm: 7.4mm; AEC Qualified: No; Voltage_Isolation_Vrms: 500VDC; Ind_H: 3.5µH; Ns1toNp: 6:6:6:2:4; DCR_ohm: 60m
TP1 TP2 TP5 TP6 TP9 TP10 TP12 TP14 = 5000: Test Point, Miniature, Red, TH; Manufacturer: Keystone; CompType: Test Point Loop; U/M: EA
TP3 TP4 TP8 TP11 TP15-TP17 = 5001: Test Point, Miniature, Black, TH; Manufacturer: Keystone; CompType: Test Point Loop; U/M: EA
TP7 = 5002: Test Point, Miniature, White, TH; Manufacturer: Keystone; CompType: Test Point Loop; ContactFinish: Silver
TP13 = 5003: Test Point, Miniature, Orange, TH; Manufacturer: Keystone; CompType: Test Point Loop; ContactFinish: Silver
U1 U4 = TPS76350QDBVRQ1: Single Output Automotive LDO, 150 mA, Fixed 5 V Output, 2.7 to 10 V Input, 5-pin SOT-23 (DBV), -40 to 125 degC, Green (RoHS & no Sb/Br); Manufacturer: Texas Instruments; Alternate PartNumber: Equivalent; Accuracy(%): 3; Fixed Output Options(V): 5.0; Iout(Max)(A): 0.15; Iq(Typ)(mA): 0.08; SubFamily: Single Channel LDO; Vdo(Typ)(mV): 300; Vin(Max)(V): 10; Vin(Min)(V): 2.7; Vout Adj(Max)(V): 5
U2 = CMP-0081540-1: Automotive Grade 2.2-MHz Wide Input Non-synchronous Boost Controller, DSS0012C (WSON-12); Alternate PartNumber: LM51551QDSSRQ1; Alternate Manufacturer: Texas Instruments; SizeAreaWB_mm2: 12; SizeZ_mm: 0.8; SizeX_mm: 2; SizeY_mm: 3; SizeArea_mm2: 6; CompType: IC; AEC Qualified: Y; AEC Category: Q200
U3 = CMP-0860764-1: 500-mA LDO With Power-Good in Small Wettable Flank WSON Package, DRB0008J (VSON-8); Manufacturer: Texas Instruments; SizeZ_mm: 1; SizeAreaWB_mm2: 16; CompType: IC; SizeArea_mm2: 9; SizeY_mm: 3; AEC Category: Q200; AEC Qualified: Y

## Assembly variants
001: all parts fitted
